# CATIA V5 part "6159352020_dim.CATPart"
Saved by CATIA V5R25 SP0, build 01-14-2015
Part number: 6159352020_dim
Source: made
Property "PROI_CREATED_ON": "12/17/2008 9:21:37 AM"
Property "BLANK_DRAWING": "--"
Property "DRAWN_BY": "FPA"
Property "FINISH": "--"
Property "HEAT_TREATMENT": "ASSIGN"
Property "MATERIAL": "ASSIGN"
Property "PROJECT": "--"
Property "PROTOTYPE_NO": "--"
Property "RELATED_DRAWING": "--"
Property "COMPLETE_MATERIAL": "ASSIGN-ASSIGN"
Property "DESCRIPTION": "Q-SHIELD 200-C"
Property "DRAWING_EXIST": "--"
Property "MANUFACTURER": "--"
Property "MANUFACTURER_2": "--"
Property "MANUFACTURER_REF": "--"
Property "TYPE_PART": "--"
Property "TODAY_DATE": "2021/06/09"
Property "PDMREV": "01.0"
Property "PDMRL": "Production"
Property "PROI_REVISION": "01"
Property "PROI_VERSION": "0"
Property "PROI_RELEASE": "Production"
Property "PTC_MODIFIED": false
Property "MFG_WP_MATERIAL": "ASSIGN"
Property "COMPANY_CODE": "---"
Property "DESCRIPTION_JP": "--"
Property "PQP_DOCUMENT": "--"
Property "GHOST": false
Property "NO_PART": false
Property "PTC_WM_ITERATION": "0"
Property "PTC_WM_VERSION": "01.0"
Property "PTC_WM_CREATED_ON": "09-Jun-21 11:28:30 AM"
Property "PTC_WM_MODIFIED_ON": "10-Jun-21 03:21:17 PM"
Property "PTC_WM_NAME": "6159352020_dim.prt"
Property "PTC_WM_NUMBER": "6159352020_DIM.PRT"
Property "PTC_WM_LIFECYCLE_STATE": "Production"
Property "PTC_WM_LIFECYCLE": "Design_Process"
Property "PTC_WM_REVISION": "01"
Property "PTC_WM_CREATED_BY": "Florian Pavageau (Grefpav) (Grefpav: CPD)"
Property "PTC_WM_MODIFIED_BY": "Florian Pavageau (Grefpav) (Grefpav: CPD)"
Property "PTC_ORGANIZATION_ID": "CPD"
Property "PTC_WM_LOCATION": "/Products/TORQUE MEASUREMENT SYSTEMS/A2010 - DELTAWRENCH GEN2/9-01-Dimensional D"
Property "PTC_WM_PART_NAME": "6159352020_dim.prt"
Property "PTC_WM_PART_NUMBER": "6159352020_DIM"
Property "PTC_WM_TEAM": "Default"
Property "EXPORT_CONTROL": "NULL"
Property "PTC_COMMON_NAME": "6159352020_dim.prt"
Property "PTC_MASTER_MATERIAL": "ASSIGN"
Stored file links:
  d:\ptc\Echange\temp\6159352020_dim.CATPart

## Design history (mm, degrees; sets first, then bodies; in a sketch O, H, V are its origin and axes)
AxisSystem1 "CS0": origin (0, 0, 0), X (1, 0, 0), Y (0, 1, 0), Z (0, 0, 1)
Set1
  DatumSurface1 "Sheet.1"
  DatumSurface2 "Sheet.2"
  DatumSurface3 "Sheet.3"
  DatumSurface4 "Sheet.4"
  DatumSurface5 "Sheet.5"
  DatumSurface6 "Sheet.6"
  DatumSurface7 "Sheet.7"
  DatumSurface8 "Sheet.8"
  Plane1 "RIGHT": stored without definition
  Plane2 "TOP": stored without definition
  Plane3 "FRONT": stored without definition
Body1 "PartBody" (main body)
